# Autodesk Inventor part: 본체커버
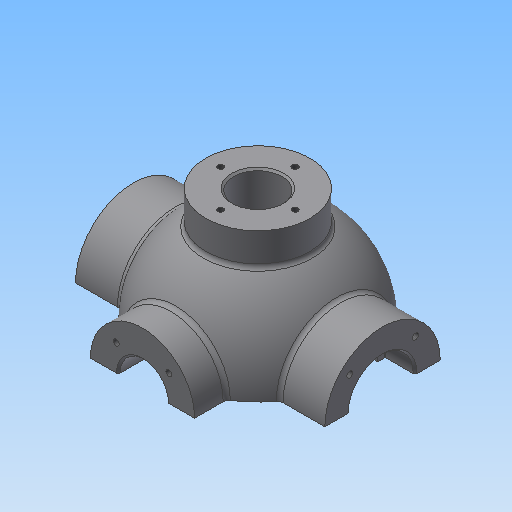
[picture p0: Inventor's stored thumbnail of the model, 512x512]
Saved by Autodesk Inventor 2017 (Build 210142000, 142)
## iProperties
Created: 2015-12
Part Number: 본체커버
Material: 일반
Document SubType Name: Modeling
Designer: mduedu
Density: 1 g/cm^3
Mass: 211.839 g
Surface Area: 451.737 cm^2
Volume: 211.839 cm^3
Appearance: 기본값
Author: mduedu
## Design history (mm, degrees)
sketch "스케치1"
  geometry: L1 (-53, 0)-(53, 0); A1 r 53 centre (0, 0) between (53, 0) and (-53, 0); 2 further points
  constraints: 2 coincident, 2 end point, 2 point on circle, 1 centre point, 1 horizontal, 1 midpoint
  dimensions: "d0" = 53 radius of A1
revolve "회전1" sketch "스케치1" stored, may be unused: angle "d2" = 90 deg
feature "쉘1" dims "d11" = 10
node "작업 평면1"
sketch "스케치2"
  geometry: C1 r 31 at (0, 0); 1 further point
  constraints: 1 centre point, 1 coincident
  dimensions: "d4" = 62 diameter of C1
extrude "돌출1" join sketch "스케치2" stored distance "d5" = 10; taper "d6" = 0 deg
node "작업 평면2"
sketch "스케치3"
  geometry: C1 r 28 at (0, 0); 1 further point
  constraints: 1 centre point, 1 coincident
  dimensions: "d8" = 56 diameter of C1
extrude "돌출2" join sketch "스케치3" stored distance "d9" = 10; taper "d10" = 0 deg
hole "구멍1" diameter "d14" = 35; stored, may be unused: countersink angle "d18" = 90 deg, drill point angle "d20" = 0 deg; dims "d12" = 10, "d13" = 10, "d15" = 6, "d16" = 4, "d17" = 2, "d19" = 16
hole "구멍2" diameter "d23" = 27; stored, may be unused: countersink angle "d27" = 90 deg, drill point angle "d29" = 0 deg; dims "d21" = 10, "d22" = 10, "d24" = 6, "d25" = 4, "d26" = 2, "d28" = 16
fillet "모깎기1" dims "d30" = 0.3
hole "구멍3" diameter "d33" = 26; stored, may be unused: countersink angle "d37" = 90 deg, drill point angle "d39" = 0 deg; dims "d31" = 10, "d32" = 10, "d34" = 6, "d35" = 4, "d36" = 2, "d38" = 16
chamfer "모따기1" distance "d40" = 1; stored, may be unused: second distance "d41" = 2, angle "d42" = 45 deg
sketch "스케치4"
  geometry: L1 (0, 0)-(0, -25); L2 (0, 0)-(-17.678, -17.678); A1 r 25 centre (0, 0) between (-17.678, -17.678) and (0, -25); 1 further point
  constraints: 4 end point, 2 point on circle, 1 centre point, 1 coincident, 1 vertical
  dimensions: "d43" = 50 diameter of A1; "d47" = 45 deg angle of L1 L2
hole "구멍4" sketch "스케치4" at (-17.678, -17.678) diameter "d49" = 3.242; stored, may be unused: countersink angle "d53" = 90 deg, drill point angle "d55" = 118 deg; dims "d50" = 11, "d51" = 4, "d52" = 2, "d54" = 13
sketch "스케치5"
  geometry: L1 (0, 0)-(0, -20); L2 (0, 0)-(-14.142, -14.142); A1 r 20 centre (0, 0) between (0, -20) and (-14.142, -14.142); 2 further points
  constraints: 4 end point, 2 coincident, 2 point on circle, 1 centre point, 1 vertical
  dimensions: "d59" = 40 diameter of A1; "d65" = 45 deg angle of L1 L2
hole "구멍5" sketch "스케치5" at (-14.142, -14.142) diameter "d67" = 3.242; stored, may be unused: countersink angle "d71" = 90 deg, drill point angle "d73" = 118 deg; dims "d68" = 8, "d69" = 4, "d70" = 2, "d72" = 10
node "작업 평면3"
sketch "스케치6"
  geometry: C1 r 65 at (0, 0); 1 further point
  constraints: 1 centre point, 1 coincident
  dimensions: "d78" = 130 diameter of C1
extrude "돌출3" join sketch "스케치6" distance "d80" = 10; taper "d81" = 0 deg
sketch "스케치7"
  geometry: C1 r 20 at (0, 0); 1 further point
  constraints: 1 centre point, 1 coincident
  dimensions: "d82" = 40 diameter of C1
extrude "돌출4" join sketch "스케치7" stored distance "d84" = 10; taper "d85" = 0 deg
sketch "스케치8"
  geometry: 2 further points
  constraints: 1 coincident
hole "구멍6" sketch "스케치8" at (0, 0) diameter "d86" = 20; stored, may be unused: countersink angle "d90" = 90 deg, drill point angle "d92" = 118 deg; dims "d87" = 7, "d88" = 40, "d89" = 5, "d91" = 10
fillet "모깎기2" dims "d93" = 0.3
sketch "스케치9"
  geometry: L1 (65, -75)-(-65, -75) reference; L2 (-45, -75)-(-38.245, -36.692); A1 r 53 centre (0, 0) between (42.988, 31) and (42.988, -31) reference; 1 further point
  constraints: 2 end point, 1 point on circle, 1 point on line
  dimensions: "d94" = 45 horizontal distance of L2.start point (0, 0); "d95" = 80 deg angle of L2 L1
feature "리브1" sketch "스케치9" dims "d96" = 1, "d97" = 8, "d98" = 0, "d99" = 0, "d100" = 1, "d101" = 1
sketch "스케치10"
  geometry: L1 (0, 0)-(0, -55); L2 (0, 0)-(-38.891, -38.891); A1 r 55 centre (0, 0) between (0, -55) and (-38.891, -38.891); 2 further points
  constraints: 4 end point, 2 coincident, 2 point on circle, 1 centre point, 1 vertical
  dimensions: "d105" = 110 diameter of A1; "d107" = 45 deg angle of L1 L2
hole "구멍7" sketch "스케치10" at (-38.891, -38.891) diameter "d109" = 10; stored, may be unused: countersink angle "d113" = 90 deg, drill point angle "d115" = 118 deg; dims "d110" = 7, "d111" = 40, "d112" = 5, "d114" = 10
fillet "모깎기3" dims "d120" = 3
fillet "모깎기4" dims "d121" = 3, "d122" = 3
fillet "모깎기5" dims "d123" = 3
fillet "모깎기6" dims "d124" = 3
sketch "스케치11"
  geometry: C1 r 5 at (-38.891, 38.891) reference; C2 r 5 at (38.891, 38.891) reference; C3 r 5 at (38.891, -38.891) reference; C4 r 5 at (-38.891, -38.891) reference; C5 r 20 at (0, 0) reference; C6 r 65 at (0, 0) reference; 1 further point
  constraints: 3 other
feature "엠보싱1" sketch "스케치11" dims "d125" = 0.5, "d126" = 0
sketch "스케치12"
  geometry: L1 (0, 100)-(0, -100); L2 (0, 100)-(-150, 100); L3 (-150, 100)-(-150, -100); L4 (-150, -100)-(0, -100); 2 further points
  constraints: 8 end point, 3 perpendicular, 1 coincident, 1 midpoint, 1 vertical
  dimensions: "d127" = 200 distance of L2.end L3.end; "d129" = 150 distance of L3.end L1.end
extrude "돌출5" cut sketch "스케치12" stored distance "d130" = 10; taper "d131" = 0 deg
sketch "스케치13"
  geometry: C1 r 7 at (0, -53); A1 r 53 centre (0, 0) between (-42.113, -32.179) and (42.113, -32.179) reference; 1 further point
  constraints: 1 centre point, 1 point on circle
  dimensions: "d132" = 14 diameter of C1
extrude "돌출6" join sketch "스케치13" distance "d133" = 5; taper "d134" = 0 deg
sketch "스케치14"
  geometry: C1 r 7 at (0, 0) reference; 1 further point
extrude "돌출7" cut sketch "스케치14" stored distance "d135" = 5; taper "d136" = 0 deg
sketch "스케치15"
  geometry: C1 r 2.25 at (0, 53); A1 r 7 centre (0, 53) between (6.965, 52.302) and (-6.965, 52.302) reference; 1 further point
  constraints: 1 centre point, 1 coincident
  dimensions: "d139" = 4.5 diameter of C1
extrude "돌출8" cut sketch "스케치15" stored distance "d141" = 5; taper "d142" = 0 deg
fillet "모깎기7" dims "d143" = 3
fillet "모깎기8" dims "d144" = 1
fillet "모깎기9" dims "d145" = 1
fillet "모깎기10" dims "d146" = 1
node "작업 평면4"
sketch "스케치16"
  geometry: C1 r 28 at (0, 0); 1 further point
  constraints: 1 centre point, 1 coincident
  dimensions: "d148" = 56 diameter of C1
extrude "돌출9" join sketch "스케치16" stored distance "d150" = 5; taper "d151" = 0 deg
hole "구멍8" diameter "d154" = 26; stored, may be unused: countersink angle "d158" = 90 deg, drill point angle "d160" = 118 deg; dims "d152" = 10, "d153" = 10, "d155" = 6, "d156" = 4, "d157" = 2, "d159" = 8
sketch "스케치17" dims "d161" = 40
  geometry: 3 further points
  constraints: 2 vertical alignment, 1 coincident, 2 other
hole "구멍9" sketch "스케치17" at (0, 20) diameter "d163" = 3.242; stored, may be unused: countersink angle "d167" = 90 deg, drill point angle "d169" = 118 deg; dims "d164" = 8, "d165" = 4, "d166" = 2, "d168" = 10
fillet "모깎기11" dims "d173" = 3
chamfer "모따기2" distance "d174" = 1; stored, may be unused: second distance "d175" = 2, angle "d176" = 45 deg
node "솔리드1"
mirror "대칭1"
mirror "대칭2"
pattern_circular "원형 패턴1" dims angle "d57" = 360 deg
mirror "대칭3"
pattern_circular "원형 패턴2" dims angle "d75" = 360 deg
pattern_circular "원형 패턴3" dims angle "d103" = 360 deg
pattern_circular "원형 패턴4" dims angle "d118" = 360 deg
pattern_circular "원형 패턴5" dims angle "d171" = 360 deg
node "투영된 루프1"
other parameters: "d3" = 67, "d7" = 62, "d77" = -85, "d147" = 62
